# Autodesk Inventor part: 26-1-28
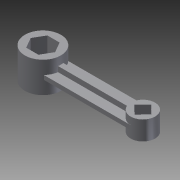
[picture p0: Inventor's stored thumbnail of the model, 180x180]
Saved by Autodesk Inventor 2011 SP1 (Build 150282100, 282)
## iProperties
Created: 2014-01
Part Number: 26-1-28
Document SubType Name: Modeling
Designer: Administrator
Density: 1 g/cm^3
Author: Administrator
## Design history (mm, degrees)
sketch "草图1"
  geometry: C1 r 17 at (0, 0); 1 further point
  constraints: 1 centre point, 1 coincident
  dimensions: "d0" = 34 diameter of C1
extrude "拉伸1" new body sketch "草图1" distance "d1" = 29; taper "d2" = 0 deg
sketch "草图2"
  geometry: L1 (11.547, 0)-(5.774, -10); L2 (5.774, -10)-(-5.774, -10); L3 (-5.774, -10)-(-11.547, 0); L4 (-11.547, 0)-(-5.774, 10); L5 (-5.774, 10)-(5.774, 10); L6 (5.774, 10)-(11.547, 0); C1 r 17 at (0, 0) reference; 1 further point
  constraints: 12 end point, 1 coincident, 13 other
  dimensions: "d3" = 20 distance between parallel lines of L5 L2
extrude "拉伸2" cut sketch "草图2" stored distance "d4" = 29; taper "d5" = 0 deg
node "工作平面1"
sketch "草图3"
  geometry: L1 (12.561, 11.456)-(94.561, 11.456); L2 (94.561, -11.544)-(12.479, -11.544); A1 r 17 centre (0, 0) between (12.561, 11.456) and (12.479, -11.544) reference; A2 r 11.5 centre (94.561, -0.044) between (94.561, -11.544) and (94.561, 11.456); 1 further point
  constraints: 4 end point, 4 point on circle, 2 tangent, 1 centre point, 1 horizontal, 1 parallel
  dimensions: "d7" = 82 distance of L1.start L1.end; "d8" = 23 diameter of A2
extrude "拉伸3" join sketch "草图3" stored distance "d9" = 4; taper "d10" = 0 deg
sketch "草图4"
  geometry: C1 r 11.5 at (94.561, -0.044); A1 r 11.5 centre (94.561, -0.044) between (94.561, -11.544) and (94.561, 11.456) reference; 1 further point
  constraints: 1 centre point, 1 coincident, 1 concentric
extrude "拉伸4" join sketch "草图4" stored distance "d11" = 18; taper "d12" = 0 deg
sketch "草图5"
  geometry: L1 (-8, -0.167)-(-0.167, 8); L2 (-0.167, 8)-(8, 0.167); L3 (8, 0.167)-(0.167, -8); L4 (0.167, -8)-(-8, -0.167); C1 r 11.5 at (0, 0) reference; 2 further points
  constraints: 8 end point, 1 coincident, 9 other
  dimensions: "d13" = 16 horizontal distance of L2.end L1.start
extrude "拉伸5" cut sketch "草图5" stored distance "d14" = 18; taper "d15" = 0 deg
sketch "草图6"
  geometry: L1 (-17, 0)-(-17, 29) reference; L2 (-83.061, 5.5)-(-83.061, 23.5) reference; L3 (-17, 21.5)-(-83.061, 21.5); L4 (-12.561, 16.5)-(-94.561, 16.5) reference; 1 further point
  constraints: 2 end point, 2 point on line, 1 perpendicular
  dimensions: "d16" = 5 distance between parallel lines of L3 L4
feature "加强筋1" sketch "草图6" dims "d17" = 1, "d18" = 5, "d19" = 0
mirror "镜像1"
node "实体1"
other parameters: "d6" = 14.5
